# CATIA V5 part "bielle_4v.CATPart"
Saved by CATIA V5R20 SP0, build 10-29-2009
Part number: bielle_4v
Bounding box of the stored display mesh (mm): x 83.173 to 140.795, y 27.417 to 140.07, z 83.509 to 156.842
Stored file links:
  D:\ecole\thinkmotion\IAO\bielle_4v.CATPart
  D:\ecole\thinkmotion\IAO\mecanisme coulisseau.CATProduct
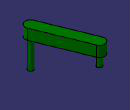
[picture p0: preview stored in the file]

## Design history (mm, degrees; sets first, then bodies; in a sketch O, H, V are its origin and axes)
Set1
  Plane1: linked copy from another document
  Point1 to Point4: linked copy from another document
  Plane2: linked copy from another document
  Point5: linked copy from another document
  Point6: linked copy from another document
  Plane3: linked copy from another document
  Plane4: linked copy from another document
Body1 (main body)
  Sketch1 on Plane1, origin (0, 0, 136.8423), H (1, 0, 0), V (0, -1, 0)
    arc A1 centre (130.7949, -37.4172) radius 10 from (121.5296, -33.655) to (140.0602, -41.1794) cw
    point P1 (130.7949, -37.4172)
    point P2 (121.5296, -33.655)
    point P3 (140.0602, -41.1794)
    reference projected point E1 (130.7949, -37.4172) from Point1
    reference projected point E2 (134.5571, -28.1519) from Point2
    arc A2 centre (93.1728, -130.0702) radius 10 from (83.9075, -126.308) to (102.4381, -133.8324) ccw
    point P4 (93.1728, -130.0702)
    point P5 (83.9075, -126.308)
    point P6 (102.4381, -133.8324)
    reference projected point E3 (93.1728, -130.0702) from Point3
    reference projected point E4 (89.4106, -139.3355) from Point4
    line L1 (140.0602, -41.1794) -> (102.4381, -133.8324)
    point P7 (140.0602, -41.1794)
    point P8 (102.4381, -133.8324)
    line L2 (83.9075, -126.308) -> (121.5296, -33.655)
    point P9 (83.9075, -126.308)
    point P10 (121.5296, -33.655)
    coincidence: P1 E1, A1 E2, P4 E3, A2 E4, P8 P6, P7 P3, P10 P2, P5 P9
    tangency: L1 A1, L1 A2, L2 A1, L2 A2
  Pad1: profile Sketch1, direction (0, 0, -1), up to Plane2
  Sketch2 on Plane1, origin (0, 0, 136.8423), H (1, 0, 0), V (0, -1, 0)
    circle A1 centre (130.7949, -37.4172) radius 5
    point P1 (130.7949, -37.4172)
    reference projected point E1 (130.7949, -37.4172) from Point1
    reference projected point E2 (132.676, -32.7845) from Point5
    coincidence: P1 E1, A1 E2
  Pad2: profile Sketch2, direction (0, 0, -1), up to Plane4
  Sketch3 on Plane1, origin (0, 0, 136.8423), H (1, 0, 0), V (0, -1, 0)
    circle A1 centre (93.1728, -130.0702) radius 5
    point P1 (93.1728, -130.0702)
    reference projected point E1 (93.1728, -130.0702) from Point3
    reference projected point E2 (91.2917, -134.7028) from Point6
    coincidence: P1 E1, A1 E2
  Pad3: profile Sketch3, direction (0, 0, -1), up to Plane3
